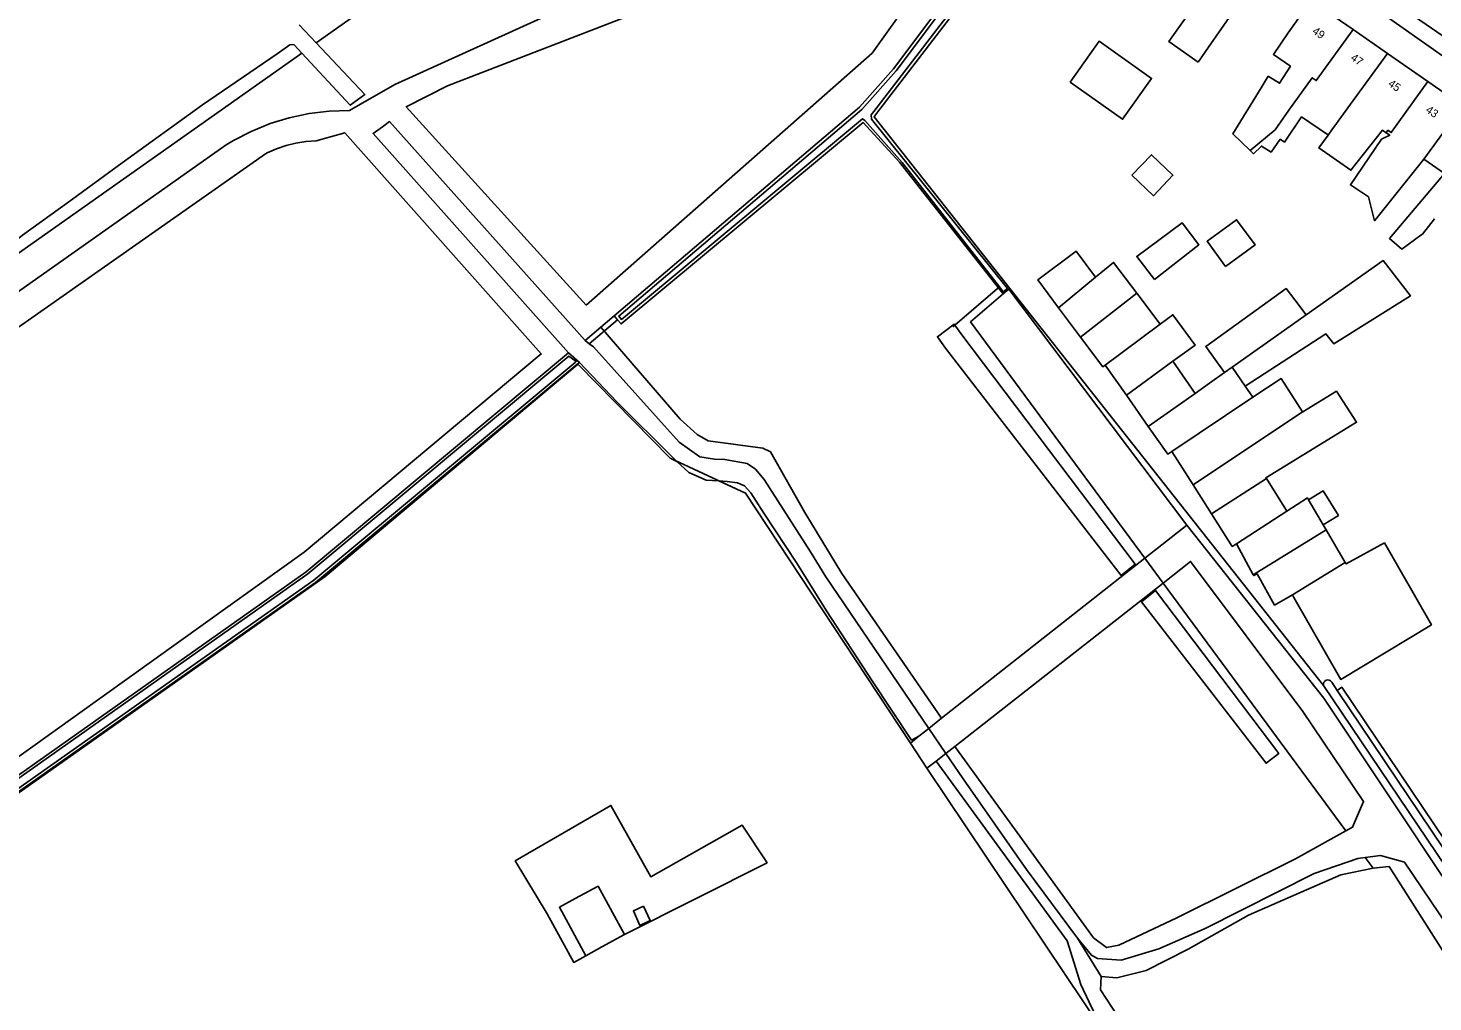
# Model space of a CAD drawing. Extents: x 163863 to 164644, y 379566 to 382155.
# Drawn here: x 164174.8 to 164350.3, y 381625.9 to 381747.5 of the extents above; entities that cross this region are included whole.
import ezdxf

# ---------------------------------------------------------------- set-up
doc = ezdxf.new("R2010")
doc.units = 0
for name, color, linetype in [('IMGEO_Bouwland', 7, 'Continuous'), ('IMGEO_Duiker', 7, 'Continuous'), ('IMGEO_Erf', 7, 'Continuous'), ('IMGEO_Grasland_overig', 7, 'Continuous'), ('IMGEO_Greppel_droge_sloot', 7, 'Continuous'), ('IMGEO_Groenvoorziening', 7, 'Continuous'), ('IMGEO_Haag', 7, 'Continuous'), ('IMGEO_Hek', 7, 'Continuous'), ('IMGEO_Loofbos', 7, 'Continuous'), ('IMGEO_Pand', 7, 'Continuous'), ('IMGEO_Pand_nummerreeks', 7, 'Continuous'), ('IMGEO_Rijbaan_lokaal_onverhard', 7, 'Continuous'), ('IMGEO_Voetpad_onverhard', 7, 'Continuous'), ('IMGEO_Voetpad_open', 7, 'Continuous'), ('IMGEO_Waterloop', 7, 'Continuous')]:
    doc.layers.add(name, color=color, linetype=linetype)

msp = doc.modelspace()

# ---------------------------------------------------------------- linework, layer by layer
at = {"layer": 'IMGEO_Bouwland'}
msp.add_lwpolyline([(164249.31, 381634.3), (164267.11, 381643.27), (164264, 381647.94), (164252.57, 381641.51), (164247.59, 381650.43), (164235.65, 381643.49), (164239.63, 381636.86), (164242.95, 381630.81), (164244.48, 381631.65)], dxfattribs=at)
at = {"layer": 'IMGEO_Duiker'}
for points in [[(164296.21, 381715.26), (164290.57, 381710.43), (164290.31, 381710.2)], [(164248.44, 381711.09), (164244.89, 381708.11)]]:
    msp.add_lwpolyline(points, dxfattribs=at)
at = {"layer": 'IMGEO_Erf'}
msp.add_lwpolyline([(164308.4, 381772.83), (164307.02, 381771.02), (164290.86, 381750), (164280.77, 381736.89), (164280.48, 381736.47), (164297.43, 381715.02)], dxfattribs=at)
at = {"layer": 'IMGEO_Grasland_overig'}
for points in [[(164285.01, 381658.22), (164264.42, 381689.42), (164261.07, 381690.98)], [(164287.33, 381660.05), (164288.9, 381661.31)], [(164287.33, 381660.05), (164289.46, 381656.93)], [(164285.01, 381658.22), (164286.07, 381659.06)], [(164287.09, 381655.07), (164285.01, 381658.22)], [(164288.22, 381655.95), (164287.09, 381655.07)], [(164309.17, 381622.09), (164287.09, 381655.07)]]:
    msp.add_lwpolyline(points, dxfattribs=at)
at = {"layer": 'IMGEO_Greppel_droge_sloot'}
msp.add_lwpolyline([(164291.43, 381709.22), (164290.57, 381710.43), (164290.47, 381710.57), (164288.39, 381708.97), (164289.4, 381707.55), (164311.33, 381679.17), (164313.1, 381680.56), (164291.43, 381709.22)], dxfattribs=at)
at = {"layer": 'IMGEO_Groenvoorziening'}
for points in [[(164297.33, 381714.93), (164297.43, 381715.02)], [(164297.43, 381715.02), (164336.62, 381665.42)], [(164341.85, 381643.92), (164342.85, 381642.58)], [(164342.85, 381642.58), (164338.8, 381641.77), (164327.26, 381636.72), (164319.71, 381632.45), (164314.46, 381629.79), (164310.8, 381628.87), (164308.85, 381629.06)], [(164342.85, 381642.58), (164344.82, 381642.8), (164360.65, 381617.95), (164365.76, 381610.9), (164374.16, 381597.69), (164373.03, 381597.19)]]:
    msp.add_lwpolyline(points, dxfattribs=at)
at = {"layer": 'IMGEO_Haag'}
msp.add_lwpolyline([(164407.8, 381604.43), (164407.63, 381605.35), (164382.05, 381601.1), (164338.92, 381665.18), (164338.35, 381664.78)], dxfattribs=at)
at = {"layer": 'IMGEO_Hek'}
for points in [[(164285.01, 381658.22), (164264.42, 381689.42), (164255.02, 381693.79), (164243.51, 381705.53), (164243.36, 381705.52)], [(164287.09, 381655.07), (164285.01, 381658.22)]]:
    msp.add_lwpolyline(points, dxfattribs=at)
at = {"layer": 'IMGEO_Loofbos'}
for points in [[(164248.93, 381772.63), (164210.77, 381745.7)], [(164016.82, 381609.1), (164084.29, 381656.42), (164208.97, 381744.42)], [(164296.62, 381714.32), (164283.66, 381730.8), (164279.12, 381735.74), (164248.87, 381710.58), (164248.44, 381711.09), (164248.01, 381711.61)], [(164288.9, 381661.31), (164276.44, 381679.42), (164271.82, 381687), (164267.52, 381694.58), (164266.6, 381695.05), (164259.73, 381695.98), (164258.36, 381696.75), (164256.26, 381698.68), (164246.32, 381710.17)], [(164288.9, 381661.31), (164314.3, 381681.31)], [(164316.58, 381678.2), (164290.56, 381657.79)], [(164339.41, 381647.23), (164316.58, 381678.2)]]:
    msp.add_lwpolyline(points, dxfattribs=at)
at = {"layer": 'IMGEO_Pand'}
for points in [[(164320.98, 381743.29), (164317.32, 381745.85), (164321.21, 381751.42), (164318.29, 381753.45), (164317.93, 381752.94), (164313.51, 381756.03), (164316.59, 381760.45), (164320.99, 381757.29), (164322.57, 381759.56), (164329.13, 381754.99), (164325.14, 381749.26), (164322.27, 381745.14), (164320.98, 381743.29)], [(164327.45, 381732.26), (164325.29, 381734.32), (164328.83, 381740.07), (164329.72, 381741.52), (164331.14, 381740.65), (164332.5, 381742.77), (164330.37, 381744.25), (164332.23, 381746.93), (164334.36, 381750), (164335.05, 381751.01), (164336.5, 381750), (164340.32, 381747.35)], [(164340.32, 381747.35), (164335.73, 381740.98), (164335.22, 381741.33), (164332.31, 381737.29), (164330.58, 381734.83), (164327.45, 381732.26)], [(164340.32, 381747.35), (164344.63, 381744.36)], [(164304.98, 381740.79), (164308.59, 381745.9), (164315.14, 381741.26), (164311.53, 381736.16), (164304.98, 381740.79)], [(164337.21, 381734.18), (164337.77, 381734.95), (164337.91, 381735.15), (164340, 381738.02), (164344.63, 381744.36)], [(164344.63, 381744.36), (164349.68, 381740.86)], [(164344.45, 381734.47), (164344.67, 381734.78), (164345.09, 381734.49), (164349.68, 381740.86)], [(164349.68, 381740.86), (164354.04, 381737.83)], [(164354.04, 381737.83), (164349.18, 381731.18)], [(164337.21, 381734.18), (164337.13, 381734.24), (164333.9, 381736.45), (164331.74, 381733.3), (164331.23, 381733.65), (164330.09, 381732.04), (164328.87, 381732.79), (164327.88, 381731.84), (164327.45, 381732.26)], [(164344.45, 381734.47), (164344, 381734.78), (164340.06, 381729.78), (164336.06, 381732.58), (164337.21, 381734.18)], [(164349.18, 381731.18), (164342.99, 381723.48), (164342.24, 381726.45), (164340, 381727.95), (164343.89, 381733.65), (164344.9, 381734.16), (164344.45, 381734.47)], [(164312.69, 381729.15), (164315.38, 381726.59), (164317.81, 381729.16), (164315.12, 381731.71), (164312.69, 381729.15)], [(164350.49, 381723.69), (164348.99, 381721.79), (164348.8, 381721.65), (164346.4, 381719.94), (164344.86, 381721.27), (164351.75, 381729.39), (164349.18, 381731.18)], [(164315.53, 381716.15), (164321.07, 381720.47), (164318.96, 381723.22), (164313.3, 381719.01), (164315.53, 381716.15)], [(164324.4, 381717.77), (164322.08, 381720.91), (164325.77, 381723.59), (164328.08, 381720.46), (164324.4, 381717.77)], [(164308.15, 381716.42), (164305.72, 381719.68), (164300.92, 381716.08), (164303.51, 381712.61)], [(164313.3, 381714.42), (164310.4, 381718.27), (164308.15, 381716.42)], [(164326.85, 381702.82), (164336.94, 381709.34), (164337.91, 381708.11), (164347.48, 381714.07), (164344.1, 381718.5), (164334.47, 381711.7)], [(164303.51, 381712.61), (164308.15, 381716.42)], [(164313.3, 381714.42), (164306.26, 381708.94)], [(164316.22, 381710.54), (164313.3, 381714.42)], [(164334.47, 381711.7), (164333.03, 381713.59), (164331.95, 381715), (164321.94, 381707.78), (164324.28, 381704.52)], [(164303.51, 381712.61), (164306.26, 381708.94)], [(164309.36, 381705.43), (164316.22, 381710.54)], [(164317.82, 381705.94), (164318.4, 381706.36), (164320.61, 381707.93), (164317.82, 381711.73), (164316.22, 381710.54)], [(164325.22, 381705.18), (164325.91, 381705.67), (164334.47, 381711.7)], [(164306.26, 381708.94), (164309.06, 381705.2), (164309.36, 381705.43)], [(164309.36, 381705.43), (164312.01, 381701.68)], [(164317.82, 381705.94), (164312.01, 381701.68)], [(164320.58, 381701.9), (164317.82, 381705.94)], [(164324.28, 381704.52), (164325.22, 381705.18)], [(164326.85, 381702.82), (164325.22, 381705.18)], [(164324.28, 381704.52), (164322.4, 381703.19), (164320.58, 381701.9)], [(164334.02, 381699.61), (164331.32, 381703.75), (164327.82, 381701.41)], [(164312.01, 381701.68), (164314.73, 381697.78)], [(164320.58, 381701.9), (164314.73, 381697.78)], [(164327.82, 381701.41), (164326.85, 381702.82)], [(164334.02, 381699.61), (164334.03, 381699.59), (164338.24, 381702.16), (164340.77, 381698.29), (164329.42, 381691.37), (164329.49, 381691.26)], [(164317.7, 381694.63), (164327.82, 381701.41)], [(164320.35, 381690.47), (164334.02, 381699.61)], [(164314.73, 381697.78), (164317.19, 381694.29), (164317.7, 381694.63)], [(164317.7, 381694.63), (164320.35, 381690.47)], [(164329.49, 381691.26), (164322.65, 381686.86)], [(164332.04, 381687.18), (164331.91, 381687.38), (164329.49, 381691.26)], [(164322.65, 381686.86), (164320.35, 381690.47)], [(164336.59, 381685.48), (164338.49, 381686.65), (164336.58, 381689.74), (164334.75, 381688.61)], [(164334.75, 381688.61), (164334.62, 381688.84), (164332.04, 381687.18)], [(164336.59, 381685.48), (164334.75, 381688.61)], [(164322.65, 381686.86), (164325.23, 381682.79), (164325.75, 381683.12)], [(164325.75, 381683.12), (164332.04, 381687.18)], [(164327.86, 381679.22), (164336.97, 381684.84)], [(164336.97, 381684.84), (164336.59, 381685.48)], [(164336.97, 381684.84), (164339.35, 381680.78)], [(164325.75, 381683.12), (164327.86, 381679.22)], [(164339.35, 381680.78), (164339.47, 381680.59), (164344.25, 381683.23), (164350.11, 381673), (164338.78, 381666.16), (164332.93, 381676.4), (164332.74, 381676.73)], [(164332.74, 381676.73), (164339.35, 381680.78)], [(164332.74, 381676.73), (164330.52, 381675.46), (164328.33, 381679.34), (164327.91, 381679.13), (164327.86, 381679.22)], [(164244.48, 381631.65), (164241.16, 381637.7), (164243.15, 381638.8), (164245.99, 381640.35), (164249.31, 381634.3)], [(164251.69, 381637.84), (164252.51, 381636.03), (164251.23, 381635.44), (164250.4, 381637.24), (164251.69, 381637.84)], [(164249.31, 381634.3), (164246.48, 381632.75), (164244.48, 381631.65)]]:
    msp.add_lwpolyline(points, dxfattribs=at)
at = {"layer": 'IMGEO_Rijbaan_lokaal_onverhard'}
for points in [[(164314.3, 381681.31), (164292.53, 381710.83), (164296.62, 381714.32)], [(164296.62, 381714.32), (164297.33, 381714.93)], [(164319.55, 381685.45), (164297.33, 381714.93)], [(164319.55, 381685.45), (164316.43, 381682.99), (164314.3, 381681.31)], [(164376.68, 381603.04), (164360.3, 381628.34), (164336.67, 381663.83), (164319.55, 381685.45)], [(164314.3, 381681.31), (164316.58, 381678.2)], [(164316.58, 381678.2), (164320.02, 381680.9), (164334.05, 381662.17), (164341.63, 381650.93), (164340.27, 381647.7), (164339.41, 381647.23)], [(164290.56, 381657.79), (164289.46, 381656.93)], [(164290.56, 381657.79), (164307.9, 381633.89), (164309.52, 381632.67), (164311.06, 381632.96), (164318.32, 381636.36), (164333.13, 381643.77), (164339.41, 381647.23)], [(164305.88, 381633.83), (164299.54, 381642.42), (164291.61, 381653.76), (164289.46, 381656.93)], [(164341.85, 381643.92), (164340.91, 381643.8), (164335.47, 381641.94), (164321.84, 381635.05), (164316.04, 381632.51), (164311.35, 381631.09), (164308.41, 381631.32), (164307.64, 381631.71), (164305.88, 381633.83)], [(164376.65, 381597.28), (164357.73, 381627.06), (164346.74, 381643.35), (164343.74, 381644.16), (164341.85, 381643.92)]]:
    msp.add_lwpolyline(points, dxfattribs=at)
at = {"layer": 'IMGEO_Voetpad_onverhard'}
for points in [[(164303.49, 381776.26), (164291.35, 381771.86), (164264.62, 381759.45), (164263.5, 381758.93), (164262.44, 381758.43), (164241.55, 381750), (164220.61, 381740.51), (164216.3, 381738.03), (164214.93, 381737.24), (164212.4, 381737.16), (164209.89, 381736.86), (164207.42, 381736.34), (164205.01, 381735.6), (164202.67, 381734.64), (164200.43, 381733.48), (164199.53, 381732.94), (164085.49, 381652.45), (164019.17, 381605.94), (164016.82, 381609.1)], [(164248.01, 381711.61), (164278.67, 381737.67), (164282.91, 381742.46), (164288.58, 381750), (164297.87, 381762.34), (164306.86, 381773.91)], [(164244.52, 381712.92), (164222.03, 381737.72), (164227.2, 381740.33), (164252.2, 381750), (164290.62, 381766.86), (164293.86, 381765.63), (164294.55, 381764.48), (164280.26, 381744.42), (164244.52, 381712.92)], [(164242.3, 381706.96), (164217.89, 381734.38), (164219.05, 381735.21), (164219.94, 381735.85), (164244.37, 381708.52)], [(164130.93, 381680.28), (164204.45, 381731.85), (164204.64, 381731.95), (164205.81, 381732.47), (164207.01, 381732.88), (164208.24, 381733.18), (164209.5, 381733.38), (164210.77, 381733.46), (164214.34, 381734.46), (164238.9, 381706.83), (164209.26, 381682.06), (164162.11, 381648.34)], [(164246.32, 381710.17), (164248.01, 381711.61)], [(164244.37, 381708.52), (164246.32, 381710.17)], [(164243.68, 381705.78), (164243.36, 381705.52), (164210.69, 381678.29), (164045.08, 381561.59), (164044.56, 381563.04), (164209.54, 381679.61), (164242.3, 381706.96)], [(164123.79, 381616.85), (164211.9, 381679.04), (164243.4, 381705.47), (164243.51, 381705.53), (164255.02, 381693.79), (164255.85, 381693.41)], [(164255.85, 381693.41), (164255.36, 381693.87), (164248.33, 381700.83), (164243.68, 381705.78)]]:
    msp.add_lwpolyline(points, dxfattribs=at)
at = {"layer": 'IMGEO_Voetpad_open'}
for points in [[(164366.58, 381736.25), (164365.24, 381734.41), (164343.09, 381750), (164341.65, 381751.02), (164341.73, 381751.2), (164335.58, 381755.47), (164335.67, 381755.63), (164322.06, 381765.02), (164322.9, 381766.25)], [(164366.58, 381736.25), (164346.56, 381750), (164322.9, 381766.25)]]:
    msp.add_lwpolyline(points, dxfattribs=at)
at = {"layer": 'IMGEO_Waterloop'}
for points in [[(164280.13, 381736.69), (164280.15, 381736.16), (164297.15, 381715.02), (164296.61, 381714.6), (164296.14, 381715.2), (164283.99, 381730.76), (164279.31, 381736.01), (164279.02, 381736.19), (164248.92, 381711.15), (164248.75, 381711.35), (164248.58, 381711.56), (164278.96, 381737.38), (164283.23, 381742.2), (164288.91, 381749.75), (164298.2, 381762.09), (164306.94, 381773.35), (164307.82, 381772.74), (164306.69, 381771.27), (164290.54, 381750.25), (164280.45, 381737.13), (164280.13, 381736.69)], [(164210.77, 381745.7), (164208.63, 381747.96)], [(164159.15, 381712.69), (164159.81, 381713.16), (164165.16, 381715.67), (164168.31, 381717.36), (164170.61, 381718.9), (164174.08, 381721.67), (164179.89, 381725.82), (164186.53, 381730.69), (164196.56, 381737.96), (164205.9, 381744.34), (164207.47, 381745.46), (164207.76, 381745.47), (164208.01, 381745.45), (164208.97, 381744.42)], [(164208.97, 381744.42), (164215.04, 381737.89), (164216.86, 381739.25), (164210.77, 381745.7)], [(164244.37, 381708.52), (164244.89, 381708.11), (164245.41, 381707.7), (164256.11, 381695.82), (164258.69, 381693.98), (164260.55, 381693.7), (164261.84, 381693.63), (164264.63, 381693.16), (164265.68, 381692.42), (164266.74, 381691.13), (164272.54, 381682.12), (164274.44, 381678.97), (164287.33, 381660.05)], [(164242.3, 381706.96), (164243.68, 381705.78)], [(164243.14, 381705.78), (164210.48, 381678.57), (164045.25, 381562.13), (164044.98, 381562.91), (164209.75, 381679.34), (164242.36, 381706.56), (164243.26, 381705.89), (164243.14, 381705.78)], [(164261.07, 381690.98), (164259.49, 381691.08), (164257.35, 381692.01), (164255.85, 381693.41)], [(164286.07, 381659.06), (164285.16, 381658.59), (164280.25, 381666), (164274.54, 381674.72), (164270.81, 381680.67), (164266.71, 381686.93), (164265.08, 381689.47), (164264.27, 381690.36), (164263.4, 381690.74), (164262.13, 381690.91), (164261.07, 381690.98)], [(164315.64, 381677.27), (164313.88, 381675.88), (164329.45, 381655.7), (164331.04, 381656.92), (164315.64, 381677.27)], [(164336.62, 381665.42), (164380.22, 381600.77)], [(164337.65, 381665.82), (164338.35, 381664.78)], [(164338.35, 381664.78), (164381.18, 381601.12)], [(164286.07, 381659.06), (164287.33, 381660.05)], [(164289.46, 381656.93), (164288.22, 381655.95)], [(164288.22, 381655.95), (164304.6, 381633.51), (164306.3, 381628.05), (164307.37, 381625.84), (164309.17, 381622.09)], [(164308.85, 381629.06), (164305.88, 381633.83)], [(164373.03, 381597.19), (164372.33, 381596.86), (164360.39, 381591.19), (164341.72, 381582.81), (164340.63, 381582.95), (164340.03, 381583.8), (164325.22, 381604.63), (164311.6, 381623.07), (164308.78, 381627.38), (164308.85, 381629.06)]]:
    msp.add_lwpolyline(points, dxfattribs=at)
msp.add_arc((164337.17, 381665.55), 0.556, 29.6547, 192.9812, dxfattribs=at)

# ---------------------------------------------------------------- texts
at = {"layer": 'IMGEO_Pand_nummerreeks'}
for s, p in [('49', (164335.14, 381746.96)), ('47', (164339.93, 381743.63)), ('45', (164344.61, 381740.39)), ('43', (164349.31, 381737.12))]:
    msp.add_text(s, height=1, rotation=325.2444, dxfattribs=at).set_placement(p)

doc.saveas('drawing.dxf')
